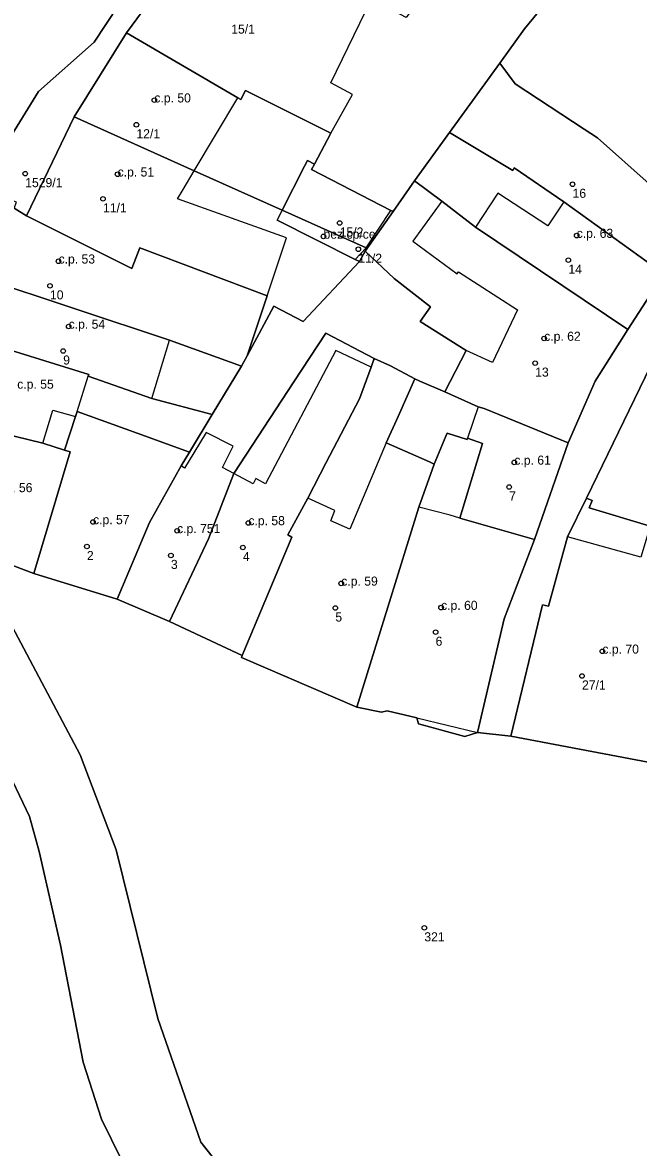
# Model space of a CAD drawing. Extents: x -878211 to -870363, y -1058464 to -1052522.
# Drawn here: x -874596.8 to -874529.1, y -1056123.6 to -1056000 of the extents above; entities that cross this region are included whole.
import ezdxf

# ---------------------------------------------------------------- set-up
doc = ezdxf.new("R2010")
doc.units = 0
for name, color, linetype in [('Vrstva 50', 7, 'Continuous'), ('Vrstva 51', 7, 'Continuous'), ('Vrstva 52', 7, 'Continuous')]:
    doc.layers.add(name, color=color, linetype=linetype)

msp = doc.modelspace()

# ---------------------------------------------------------------- linework, layer by layer
at = {"layer": 'Vrstva 50'}
for centre in [(-874582.34, -1056008.50994), (-874584.31, -1056011.20994), (-874596.53, -1056016.57994), (-874586.38, -1056016.64994), (-874536.38, -1056017.74994), (-874587.98, -1056019.34994), (-874561.97, -1056022.00994), (-874563.75, -1056023.47994), (-874535.93, -1056023.38994), (-874559.92, -1056024.88994), (-874592.87, -1056026.20994), (-874536.84, -1056026.08994), (-874593.81, -1056028.90994), (-874591.76, -1056033.36994), (-874539.5, -1056034.69994), (-874592.36, -1056036.06994), (-874540.49, -1056037.39994), (-874542.78, -1056048.30994), (-874543.35, -1056051.00994), (-874589.08, -1056054.84994), (-874572.01, -1056054.95994), (-874579.84, -1056055.82994), (-874589.75, -1056057.54994), (-874572.61, -1056057.65994), (-874580.52, -1056058.52994), (-874561.8, -1056061.59994), (-874562.45, -1056064.29994), (-874550.83, -1056064.25994), (-874551.43, -1056066.95994), (-874533.1, -1056069.06994), (-874535.34, -1056071.76994), (-874552.67, -1056099.43994)]:
    msp.add_circle(centre, 0.25, dxfattribs=at)
at = {"layer": 'Vrstva 51'}
for points in [[(-874607.11, -1056035.8), (-874603.24, -1056025.63), (-874601.15, -1056017.38), (-874595.08, -1056007.57), (-874588.97, -1056002.13), (-874576.82, -1055983.77)], [(-874576.82, -1055983.77), (-874588.97, -1056002.13), (-874595.08, -1056007.57), (-874601.15, -1056017.38)], [(-874527.62, -1055996.25), (-874531.18, -1055994.73), (-874533.01, -1055998.94), (-874538.4, -1055996.31), (-874538.77, -1055997.12), (-874541.68, -1056000.66), (-874544.39, -1056004.44), (-874542.68, -1056006.73), (-874535.12, -1056011.69), (-874533.65, -1056012.64), (-874527.95, -1056017.69)], [(-874597.75, -1056020.37), (-874596.38, -1056021.2), (-874591.16, -1056010.34), (-874585.41, -1056001.12), (-874581.9, -1055996.31)], [(-874526.35, -1056027.59), (-874530.32, -1056033.69), (-874533.91, -1056039.37), (-874536.88, -1056046.17), (-874540.56, -1056056.79), (-874543.89, -1056065.49), (-874546.82, -1056077.98), (-874543.16, -1056078.38), (-874539.7, -1056063.97), (-874539.04, -1056064.11), (-874536.92, -1056056.49), (-874534.86, -1056052.24), (-874526.63, -1056035.33)], [(-874526.63, -1056035.33), (-874534.86, -1056052.24), (-874534.24, -1056052.51), (-874534.56, -1056053.29), (-874527.85, -1056055.3)], [(-874572.41, -1056129.1), (-874577.24, -1056122.98), (-874581.96, -1056109.39), (-874586.54, -1056090.87), (-874590.48, -1056080.42), (-874598.29, -1056065.73), (-874606.18, -1056058.17), (-874610.25, -1056053.12), (-874611.9, -1056049.46), (-874612.07, -1056046.08), (-874608.97, -1056041.4), (-874607.11, -1056035.8)], [(-874526.7, -1056081.48), (-874543.16, -1056078.38), (-874546.82, -1056077.98), (-874548.22, -1056078.42), (-874553.31, -1056077.04), (-874553.48, -1056076.38), (-874556.77, -1056075.6), (-874557.36, -1056075.74), (-874560.1, -1056075.19), (-874572.76, -1056069.74), (-874572.69, -1056069.51), (-874580.68, -1056065.78), (-874586.42, -1056063.34), (-874595.58, -1056060.53), (-874605.95, -1056056.6), (-874606.18, -1056058.17), (-874598.29, -1056065.73), (-874590.48, -1056080.42), (-874586.54, -1056090.87), (-874581.96, -1056109.39), (-874577.24, -1056122.98), (-874572.41, -1056129.1)], [(-874599.02, -1056081), (-874596.05, -1056087.2), (-874595.01, -1056091.04), (-874592.66, -1056101.34), (-874590.15, -1056114.19), (-874588.13, -1056120.47), (-874584.81, -1056127.24)], [(-874584.81, -1056127.24), (-874588.13, -1056120.47), (-874590.15, -1056114.19), (-874592.66, -1056101.34), (-874595.01, -1056091.04), (-874596.05, -1056087.2), (-874599.02, -1056081)]]:
    msp.add_lwpolyline(points, dxfattribs=at)
for points in [[(-874556.11, -1056020.76), (-874553.75, -1056017.38), (-874549.89, -1056012.05), (-874544.39, -1056004.44), (-874541.68, -1056000.66), (-874538.77, -1055997.12), (-874548.4, -1055991.44), (-874548.71, -1055991.26), (-874554.68, -1055999.42), (-874558.49, -1055997.38), (-874559.64, -1055996.81), (-874575.45, -1055988.5), (-874580.84, -1055997), (-874581.9, -1055996.31), (-874585.41, -1056001.12), (-874573.16, -1056008.25), (-874572.84, -1056008.44), (-874572.34, -1056007.45), (-874562.93, -1056012.12), (-874564.74, -1056015.53), (-874565.07, -1056016.14), (-874556.35, -1056020.64)], [(-874585.41, -1056001.12), (-874591.16, -1056010.34), (-874577.95, -1056016.27), (-874568.28, -1056020.61), (-874565.83, -1056015.75), (-874565.52, -1056015.14), (-874564.74, -1056015.53), (-874562.93, -1056012.12), (-874572.34, -1056007.45), (-874572.84, -1056008.44), (-874573.16, -1056008.25)], [(-874535.12, -1056011.69), (-874542.68, -1056006.73), (-874544.39, -1056004.44), (-874549.89, -1056012.05), (-874542.96, -1056016.22), (-874542.79, -1056015.95), (-874537.35, -1056019.67), (-874526.35, -1056027.59), (-874522.37, -1056021.31), (-874527.95, -1056017.69), (-874533.65, -1056012.64)], [(-874577.95, -1056016.27), (-874591.16, -1056010.34), (-874596.38, -1056021.2), (-874584.83, -1056027.02), (-874583.95, -1056024.74), (-874569.95, -1056030.02), (-874572.14, -1056036.6), (-874569.2, -1056031.16), (-874566, -1056032.82), (-874559.81, -1056026.25), (-874560.26, -1056026.03), (-874568.83, -1056021.71), (-874568.28, -1056020.61)], [(-874542.79, -1056015.95), (-874542.96, -1056016.22), (-874549.89, -1056012.05), (-874553.75, -1056017.38), (-874550.74, -1056019.59), (-874547.06, -1056022.48), (-874530.32, -1056033.69), (-874526.35, -1056027.59), (-874537.35, -1056019.67)], [(-874556.11, -1056020.76), (-874556.35, -1056020.64), (-874565.07, -1056016.14), (-874564.74, -1056015.53), (-874565.52, -1056015.14), (-874565.83, -1056015.75), (-874568.28, -1056020.61), (-874559.06, -1056024.74), (-874560.26, -1056026.03), (-874559.81, -1056026.25), (-874559.16, -1056025.1)], [(-874559.16, -1056025.1), (-874555.97, -1056028.09), (-874552, -1056031.2), (-874553.11, -1056032.82), (-874548.09, -1056036.02), (-874550.42, -1056040.57), (-874546.74, -1056042.22), (-874546.09, -1056042.39), (-874536.88, -1056046.17), (-874533.91, -1056039.37), (-874530.32, -1056033.69), (-874547.06, -1056022.48), (-874550.74, -1056019.59), (-874553.75, -1056017.38), (-874556.11, -1056020.76)], [(-874597.75, -1056020.37), (-874597.5, -1056019.73), (-874598.56, -1056019.33), (-874601.45, -1056027.99), (-874580.69, -1056034.88), (-874572.76, -1056037.74), (-874572.14, -1056036.6), (-874569.95, -1056030.02), (-874583.95, -1056024.74), (-874584.83, -1056027.02), (-874596.38, -1056021.2)], [(-874559.06, -1056024.74), (-874568.28, -1056020.61), (-874568.83, -1056021.71), (-874560.26, -1056026.03)], [(-874563.51, -1056034.12), (-874558.19, -1056036.89), (-874556.4, -1056037.7), (-874553.73, -1056039.14), (-874553.15, -1056039.4), (-874550.42, -1056040.57), (-874548.09, -1056036.02), (-874553.11, -1056032.82), (-874552, -1056031.2), (-874555.97, -1056028.09), (-874559.16, -1056025.1), (-874559.81, -1056026.25), (-874566, -1056032.82), (-874569.2, -1056031.16), (-874572.14, -1056036.6), (-874572.76, -1056037.74), (-874575.97, -1056043.04), (-874578.49, -1056047.19), (-874579.41, -1056048.7), (-874582.86, -1056054.91), (-874586.42, -1056063.34), (-874580.68, -1056065.78), (-874576.38, -1056056.72), (-874573.6, -1056049.54), (-874567.01, -1056039.47)], [(-874601.45, -1056027.99), (-874603.59, -1056034.29), (-874589.54, -1056038.66), (-874589.62, -1056038.82), (-874582.61, -1056041.29), (-874575.97, -1056043.04), (-874572.76, -1056037.74), (-874580.69, -1056034.88)], [(-874604.1, -1056043.88), (-874594.59, -1056046.18), (-874592.21, -1056046.96), (-874591, -1056043.26), (-874590.82, -1056042.71), (-874584.23, -1056045.11), (-874578.49, -1056047.19), (-874575.97, -1056043.04), (-874582.61, -1056041.29), (-874589.62, -1056038.82), (-874589.54, -1056038.66), (-874603.59, -1056034.29), (-874603.8, -1056034.12), (-874604.34, -1056037.2), (-874604.13, -1056037.25), (-874605.38, -1056042.97), (-874604.9, -1056043.7)], [(-874572.69, -1056069.51), (-874567.23, -1056056.51), (-874567.66, -1056056.28), (-874565.49, -1056052.25), (-874563.47, -1056048.32), (-874559.79, -1056041.31), (-874558.52, -1056037.84), (-874558.19, -1056036.89), (-874563.51, -1056034.12), (-874567.01, -1056039.47), (-874573.6, -1056049.54), (-874576.38, -1056056.72), (-874580.68, -1056065.78)], [(-874572.76, -1056069.74), (-874560.1, -1056075.19), (-874553.27, -1056053.24), (-874551.59, -1056048.49), (-874552.11, -1056048.23), (-874556.87, -1056046.17), (-874555.55, -1056043.25), (-874553.73, -1056039.14), (-874556.4, -1056037.7), (-874558.19, -1056036.89), (-874558.52, -1056037.84), (-874559.79, -1056041.31), (-874563.47, -1056048.32), (-874565.49, -1056052.25), (-874567.66, -1056056.28), (-874567.23, -1056056.51), (-874572.69, -1056069.51)], [(-874551.59, -1056048.49), (-874550.29, -1056045.41), (-874550.16, -1056045.11), (-874547.97, -1056045.78), (-874547.91, -1056045.65), (-874546.27, -1056046.22), (-874548.76, -1056054.42), (-874540.56, -1056056.79), (-874536.88, -1056046.17), (-874546.09, -1056042.39), (-874546.74, -1056042.22), (-874550.42, -1056040.57), (-874553.15, -1056039.4), (-874553.73, -1056039.14), (-874555.55, -1056043.25), (-874556.87, -1056046.17), (-874552.11, -1056048.23)], [(-874579.41, -1056048.7), (-874578.49, -1056047.19), (-874584.23, -1056045.11), (-874590.82, -1056042.71), (-874591, -1056043.26), (-874592.21, -1056046.96), (-874591.59, -1056047.16), (-874595.58, -1056060.53), (-874586.42, -1056063.34), (-874582.86, -1056054.91)], [(-874604.1, -1056043.88), (-874605.95, -1056056.6), (-874595.58, -1056060.53), (-874591.59, -1056047.16), (-874592.21, -1056046.96), (-874594.59, -1056046.18)], [(-874557.36, -1056075.74), (-874556.77, -1056075.6), (-874553.48, -1056076.38), (-874553.31, -1056077.04), (-874548.22, -1056078.42), (-874546.82, -1056077.98), (-874543.89, -1056065.49), (-874540.56, -1056056.79), (-874548.76, -1056054.42), (-874546.27, -1056046.22), (-874547.91, -1056045.65), (-874547.97, -1056045.78), (-874550.16, -1056045.11), (-874550.29, -1056045.41), (-874551.59, -1056048.49), (-874553.27, -1056053.24), (-874560.1, -1056075.19)], [(-874526.7, -1056081.48), (-874524.23, -1056069.2), (-874523.5, -1056069.42), (-874521.27, -1056063.96), (-874520.23, -1056061.41), (-874522.24, -1056060.65), (-874521.2, -1056057.32), (-874527.85, -1056055.3), (-874534.56, -1056053.29), (-874534.24, -1056052.51), (-874534.86, -1056052.24), (-874536.92, -1056056.49), (-874539.04, -1056064.11), (-874539.7, -1056063.97), (-874543.16, -1056078.38)]]:
    msp.add_lwpolyline(points, close=True, dxfattribs=at)
at = {"layer": 'Vrstva 52'}
for points in [[(-874572.84, -1056008.44), (-874572.34, -1056007.45), (-874562.93, -1056012.12), (-874560.56, -1056007.9), (-874562.93, -1056006.62), (-874558.49, -1055997.38), (-874559.64, -1055996.81), (-874575.45, -1055988.5), (-874580.84, -1055997), (-874581.9, -1055996.31), (-874585.41, -1056001.12), (-874573.16, -1056008.25)], [(-874591.16, -1056010.34), (-874577.95, -1056016.27), (-874573.16, -1056008.25), (-874585.41, -1056001.12)], [(-874596.38, -1056021.2), (-874584.83, -1056027.02), (-874583.95, -1056024.74), (-874569.95, -1056030.02), (-874567.83, -1056023.63), (-874579.79, -1056019.35), (-874579.19, -1056018.34), (-874577.95, -1056016.27), (-874591.16, -1056010.34)], [(-874568.28, -1056020.61), (-874568.83, -1056021.71), (-874560.26, -1056026.03), (-874559.06, -1056024.74), (-874556.35, -1056020.64), (-874565.07, -1056016.14), (-874564.74, -1056015.53), (-874565.52, -1056015.14), (-874565.83, -1056015.75)], [(-874601.45, -1056027.99), (-874580.69, -1056034.88), (-874572.76, -1056037.74), (-874572.14, -1056036.6), (-874569.95, -1056030.02), (-874583.95, -1056024.74), (-874584.83, -1056027.02), (-874596.38, -1056021.2), (-874597.75, -1056020.37), (-874597.5, -1056019.73), (-874598.56, -1056019.33)], [(-874544.58, -1056018.73), (-874547.06, -1056022.48), (-874530.32, -1056033.69), (-874526.35, -1056027.59), (-874537.35, -1056019.67), (-874539.09, -1056022.32)], [(-874550.74, -1056019.59), (-874553.95, -1056024), (-874549.07, -1056027.58), (-874548.9, -1056027.38), (-874542.44, -1056031.55), (-874545.17, -1056037.33), (-874548.09, -1056036.02), (-874550.42, -1056040.57), (-874546.74, -1056042.22), (-874546.09, -1056042.39), (-874536.88, -1056046.17), (-874533.91, -1056039.37), (-874530.32, -1056033.69), (-874547.06, -1056022.48)], [(-874603.59, -1056034.29), (-874589.54, -1056038.66), (-874589.62, -1056038.82), (-874582.61, -1056041.29), (-874580.69, -1056034.88), (-874601.45, -1056027.99)], [(-874605.38, -1056042.97), (-874604.9, -1056043.7), (-874604.1, -1056043.88), (-874594.59, -1056046.18), (-874593.51, -1056042.55), (-874591, -1056043.26), (-874590.82, -1056042.71), (-874589.62, -1056038.82), (-874589.54, -1056038.66), (-874603.59, -1056034.29), (-874603.8, -1056034.12), (-874604.34, -1056037.2), (-874604.13, -1056037.25)], [(-874580.68, -1056065.78), (-874572.69, -1056069.51), (-874567.23, -1056056.51), (-874567.66, -1056056.28), (-874565.49, -1056052.25), (-874563.47, -1056048.32), (-874559.79, -1056041.31), (-874558.52, -1056037.84), (-874562.38, -1056036.01), (-874570.12, -1056050.65), (-874571.17, -1056050.09), (-874571.49, -1056050.67), (-874573.6, -1056049.54), (-874576.38, -1056056.72)], [(-874595.58, -1056060.53), (-874586.42, -1056063.34), (-874582.86, -1056054.91), (-874579.41, -1056048.7), (-874578.49, -1056047.19), (-874584.23, -1056045.11), (-874590.82, -1056042.71), (-874591, -1056043.26), (-874592.21, -1056046.96), (-874591.59, -1056047.16)], [(-874546.27, -1056046.22), (-874548.76, -1056054.42), (-874540.56, -1056056.79), (-874536.88, -1056046.17), (-874546.09, -1056042.39), (-874546.74, -1056042.22), (-874547.91, -1056045.65)], [(-874605.95, -1056056.6), (-874595.58, -1056060.53), (-874591.59, -1056047.16), (-874592.21, -1056046.96), (-874594.59, -1056046.18), (-874604.1, -1056043.88)], [(-874586.42, -1056063.34), (-874580.68, -1056065.78), (-874576.38, -1056056.72), (-874573.6, -1056049.54), (-874574.86, -1056048.88), (-874573.67, -1056046.52), (-874576.64, -1056045.01), (-874578.01, -1056047.27), (-874579.02, -1056048.94), (-874579.41, -1056048.7), (-874582.86, -1056054.91)], [(-874572.69, -1056069.51), (-874572.76, -1056069.74), (-874560.1, -1056075.19), (-874553.27, -1056053.24), (-874551.59, -1056048.49), (-874552.11, -1056048.23), (-874556.87, -1056046.17), (-874560.87, -1056055.66), (-874562.94, -1056054.74), (-874562.5, -1056053.58), (-874565.49, -1056052.25), (-874567.66, -1056056.28), (-874567.23, -1056056.51)], [(-874553.27, -1056053.24), (-874560.1, -1056075.19), (-874557.36, -1056075.74), (-874556.77, -1056075.6), (-874553.48, -1056076.38), (-874546.82, -1056077.98), (-874543.89, -1056065.49), (-874540.56, -1056056.79), (-874548.76, -1056054.42), (-874549.83, -1056054.11)], [(-874543.16, -1056078.38), (-874526.7, -1056081.48), (-874524.23, -1056069.2), (-874523.5, -1056069.42), (-874521.27, -1056063.96), (-874520.23, -1056061.41), (-874522.24, -1056060.65), (-874521.2, -1056057.32), (-874527.85, -1056055.3), (-874528.89, -1056058.73), (-874536.92, -1056056.49), (-874539.04, -1056064.11), (-874539.7, -1056063.97)]]:
    msp.add_lwpolyline(points, close=True, dxfattribs=at)

# ---------------------------------------------------------------- texts
at = {"layer": 'Vrstva 50'}
for s, height, p in [('15/1', 0.999996, (-874573.89, -1056001.199)), ('c.p. 50', 0.999996, (-874582.34, -1056008.76)), ('12/1', 0.999996, (-874584.31, -1056012.699)), ('c.p. 51', 0.999996, (-874586.38, -1056016.899)), ('1529/1', 0.999996, (-874596.53, -1056018.069)), ('16', 0.999996, (-874536.38, -1056019.239)), ('11/1', 0.999996, (-874587.98, -1056020.839)), ('bez cp/ce', 0.999996, (-874563.75, -1056023.73)), ('15/2', 0.999996, (-874561.97, -1056023.499)), ('c.p. 63', 0.999996, (-874535.93, -1056023.639)), ('c.p. 53', 0.999996, (-874592.87, -1056026.46)), ('11/2', 0.999996, (-874559.92, -1056026.379)), ('14', 0.999996, (-874536.84, -1056027.579)), ('10', 0.999996, (-874593.81, -1056030.399)), ('c.p. 54', 0.999996, (-874591.76, -1056033.62)), ('c.p. 62', 0.999996, (-874539.5, -1056034.95)), ('9', 1, (-874592.36, -1056037.559)), ('13', 0.999996, (-874540.49, -1056038.889)), ('c.p. 55', 0.999996, (-874597.41, -1056040.21)), ('c.p. 61', 0.999996, (-874542.78, -1056048.56)), ('c.p. 56', 0.999996, (-874599.75, -1056051.58)), ('7', 1, (-874543.35, -1056052.499)), ('c.p. 57', 0.999996, (-874589.08, -1056055.1)), ('c.p. 751', 0.999996, (-874579.84, -1056056.08)), ('c.p. 58', 0.999996, (-874572.01, -1056055.21)), ('2', 1, (-874589.75, -1056059.039)), ('4', 1, (-874572.61, -1056059.149)), ('3', 1, (-874580.52, -1056060.019)), ('c.p. 59', 0.999996, (-874561.8, -1056061.85)), ('c.p. 60', 0.999996, (-874550.83, -1056064.51)), ('5', 1, (-874562.45, -1056065.789)), ('6', 1, (-874551.43, -1056068.449)), ('c.p. 70', 0.999996, (-874533.1, -1056069.32)), ('27/1', 0.999996, (-874535.34, -1056073.259)), ('321', 0.999996, (-874552.67, -1056100.929))]:
    msp.add_text(s, height=height, dxfattribs=at).set_placement(p)

doc.saveas('drawing.dxf')
